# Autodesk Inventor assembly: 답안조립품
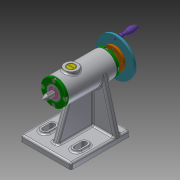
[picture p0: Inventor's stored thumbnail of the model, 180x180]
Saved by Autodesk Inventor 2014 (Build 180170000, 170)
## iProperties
Created: 2019-10
Part Number: 답안조립품
Document SubType Name: Assembly
Designer: kh
Author: kh
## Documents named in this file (18)
- C:\Users\kh\Desktop\491004V1006\답안조립품.iam
- C:\Users\kh\Desktop\491004V1006\본체.ipt
- C:\Users\kh\Desktop\491004V1006\나사.ipt
- C:\Users\kh\Desktop\491004V1006\나사축.ipt
- C:\Users\kh\Desktop\491004V1006\너트 M8.ipt
- C:\Users\kh\Desktop\491004V1006\돌림판.ipt
- C:\Users\kh\Desktop\491004V1006\멈춤나사 M3.ipt
- C:\Users\kh\Desktop\491004V1006\볼트 M3.ipt
- C:\Users\kh\Desktop\491004V1006\부시.ipt
- C:\Users\kh\Desktop\491004V1006\센터.ipt
- C:\Users\kh\Desktop\491004V1006\센터홀더.ipt
- C:\Users\kh\Desktop\491004V1006\슬리브.ipt
- C:\Users\kh\Desktop\491004V1006\와셔.ipt
- C:\Users\kh\Desktop\491004V1006\중공축.ipt
- C:\Users\kh\Desktop\491004V1006\커버.ipt
- C:\Users\kh\Desktop\491004V1006\키 4 x 4 x 10.ipt
- C:\Users\kh\Desktop\491004V1006\플랜지.ipt
- C:\Users\kh\Desktop\491004V1006\핸들.ipt
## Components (2 placed, 2 different names)
1. 플랜지:1 — Insert:12, Mate:1, Insert:13, Insert:15, Insert:16
2. 핸들:1 — Insert:18
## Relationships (6: Insert 5, Mate 1)
- Insert:12: 플랜지:1
- Mate:1: 플랜지:1
- Insert:13: 플랜지:1
- Insert:15: 플랜지:1
- Insert:16: 플랜지:1
- Insert:18: 핸들:1
